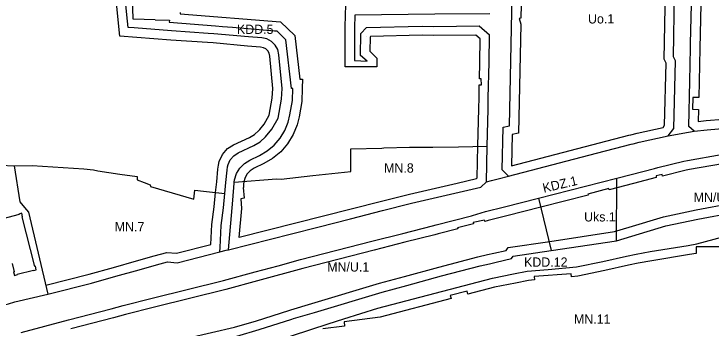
# Model space of a CAD drawing. Extents: x 7414808 to 7417449, y 5544732 to 5546764.
# Drawn here: x 7415519.6 to 7415895.6, y 5545891.1 to 5546060.4 of the extents above; entities that cross this region are included whole.
import ezdxf

# ---------------------------------------------------------------- set-up
doc = ezdxf.new("R2010")
doc.units = 0
for name, color, linetype in [('LIN_Linie Rozgraniczajace', 7, 'Continuous'), ('LIN_nieprzekraczale linie zabudowy', 7, 'Continuous'), ('LIN_obowiązujące linie zabudowy', 7, 'Continuous'), ('TXT_Oznaczenia Przeznaczenia', 7, 'Continuous')]:
    doc.layers.add(name, color=color, linetype=linetype)

msp = doc.modelspace()

# ---------------------------------------------------------------- linework, layer by layer
at = {"layer": 'LIN_Linie Rozgraniczajace'}
for p, q in [((7415595.79, 5546057.22), (7415583.85, 5546057.58)), ((7415774.51, 5545969.95), (7415774.77, 5545989.18))]:
    msp.add_line(p, q, dxfattribs=at)
for points in [[(7415786.28, 5545973), (7415782.94, 5545976.32), (7415783.43, 5545999.34), (7415786.84, 5546000.16), (7415788.5, 5546079.24), (7415788.63, 5546085.44), (7415785.3, 5546088.86)], [(7415872.46, 5545994.8), (7415875.55, 5545998.59), (7415876.38, 5546035.06), (7415875.3, 5546037.23), (7415875.94, 5546071.67), (7415877.25, 5546073.42), (7415877.59, 5546088.6)], [(7415583.85, 5546057.58), (7415583.43, 5546075.3), (7415573.8, 5546078.32), (7415564.97, 5546079.11), (7415559.81, 5546079.62), (7415556.94, 5546079.1), (7415546.52, 5546080.39), (7415513.83, 5546084.43), (7415510.82, 5546081.8), (7415559.62, 5546075.78), (7415564.88, 5546077.31), (7415573.69, 5546075.93), (7415579.48, 5546070.64)], [(7415886.52, 5545997.16), (7415883.58, 5545999.68), (7415884.13, 5546024.12), (7415884.54, 5546042.1), (7415884.6, 5546044.49), (7415885.08, 5546065.59), (7415885.49, 5546083.7)], [(7415581.19, 5546053.19), (7415580.8, 5546056.61), (7415579.98, 5546065.34)], [(7415776.33, 5546060.55), (7415746.7, 5546060.31), (7415703.42, 5546059.82), (7415703.26, 5546052.85)], [(7415595.79, 5546057.22), (7415603.45, 5546057.06), (7415603.37, 5546056.07), (7415628.32, 5546054.09), (7415632.14, 5546053.73), (7415637.4, 5546053.25)], [(7415709.7, 5546053.2), (7415739.75, 5546053.91), (7415746.1, 5546053.72), (7415770.52, 5546053.93), (7415776.17, 5546049.22)], [(7415633.35, 5545963.71), (7415633.92, 5545969.5), (7415634.52, 5545976.22), (7415634.79, 5545977.98), (7415635.09, 5545979.29), (7415636.26, 5545981.86), (7415638.11, 5545983.99), (7415640.48, 5545985.52), (7415648.92, 5545989.43), (7415652.36, 5545991.46), (7415655.35, 5545994.12), (7415658.73, 5545998.23), (7415662.07, 5546004.15), (7415663.88, 5546014.5), (7415664.25, 5546020.31), (7415662.54, 5546038.46), (7415661.88, 5546041.21), (7415660.49, 5546043.66), (7415658.46, 5546045.62), (7415655.97, 5546046.94), (7415653.37, 5546047.5), (7415646.05, 5546048.07), (7415627.36, 5546049.75), (7415624.37, 5546049.96), (7415604.61, 5546051.36), (7415584.37, 5546052.96), (7415581.19, 5546053.19)], [(7415637.4, 5546053.25), (7415660.17, 5546051.39), (7415661.34, 5546051.29)], [(7415638.44, 5545969.7), (7415638.62, 5545971.07), (7415639.68, 5545974.36), (7415641.47, 5545977.32), (7415643.89, 5545979.79), (7415646.81, 5545981.64), (7415651.96, 5545984.12), (7415656.18, 5545986.61), (7415659.95, 5545989.74), (7415663.15, 5545993.44), (7415665.7, 5545997.61), (7415667.55, 5546002.15), (7415668.48, 5546005.98), (7415669.85, 5546013.79), (7415670.05, 5546020.27), (7415669.32, 5546020.27), (7415666.3, 5546046.51), (7415662.53, 5546050.29), (7415661.34, 5546051.29)], [(7415703.26, 5546052.85), (7415703.22, 5546035.29), (7415710.15, 5546035.03), (7415706.44, 5546037.97), (7415706.75, 5546049.91), (7415709.7, 5546053.2)], [(7415774.77, 5545989.18), (7415775.35, 5546009.15), (7415775.46, 5546015.21), (7415775.86, 5546034.18), (7415776.17, 5546049.22)], [(7415872.46, 5545994.8), (7415883.51, 5545996.64), (7415886.52, 5545997.16)], [(7415886.52, 5545997.16), (7415893.57, 5545997.99), (7415916.2, 5545999.89)], [(7415786.28, 5545973), (7415829.7, 5545984.27), (7415852.48, 5545990.18), (7415853.52, 5545990.42), (7415856.87, 5545991.21), (7415872.46, 5545994.8)], [(7415638.44, 5545969.7), (7415661.14, 5545971.45), (7415663.73, 5545971.34), (7415680.75, 5545973.37), (7415701.28, 5545975.47), (7415701.34, 5545987.72), (7415717.94, 5545988.14), (7415719.06, 5545988.16), (7415732.87, 5545988.55), (7415737.16, 5545988.56), (7415745.56, 5545988.58), (7415759.37, 5545988.87), (7415774.77, 5545989.18)], [(7415844.76, 5545971.84), (7415852.47, 5545973.82), (7415865.1, 5545977.09), (7415866.9, 5545977.56), (7415880.97, 5545980.98), (7415882.96, 5545981.47), (7415901.09, 5545984.65), (7415911.16, 5545985.54), (7415914.44, 5545985.83), (7415927.64, 5545986.05), (7415944.27, 5545986.35), (7415954.23, 5545986.43), (7415968.21, 5545986.01), (7415974.4, 5545985.57), (7415988.52, 5545984.56)], [(7415512.41, 5545978.97), (7415519.74, 5545978.47)], [(7415519.74, 5545978.47), (7415529.45, 5545978.65), (7415546.1, 5545977.59), (7415557.27, 5545976.87), (7415562.46, 5545976.39), (7415564.78, 5545975.77), (7415576.64, 5545974.08), (7415586.04, 5545972.73), (7415586.03, 5545971.04), (7415589.78, 5545969.57), (7415593.1, 5545968.28), (7415593.23, 5545967.31), (7415616.56, 5545960.53), (7415617.16, 5545965.37), (7415621.84, 5545964.84), (7415633.35, 5545963.71)], [(7415519.74, 5545978.47), (7415522.67, 5545959.21), (7415525.28, 5545956.13), (7415527.46, 5545953.55), (7415537.93, 5545909.37)], [(7415774.51, 5545969.95), (7415777.24, 5545970.65), (7415780.77, 5545971.57), (7415786.28, 5545973)], [(7415802.62, 5545961.02), (7415844.76, 5545971.84)], [(7415844.58, 5545938.19), (7415852.82, 5545940.7), (7415871.18, 5545946.15), (7415888.53, 5545949.83), (7415907.71, 5545953.42), (7415917.62, 5545955.43), (7415930.1, 5545957.84), (7415946.29, 5545960.61), (7415967.66, 5545962.35), (7415973.92, 5545962.82), (7415980.78, 5545963.53), (7415981.89, 5545963.65), (7415985.36, 5545964.57), (7415992.58, 5545970.49), (7415994.76, 5545972.26)], [(7415844.58, 5545938.19), (7415844.76, 5545971.84)], [(7415635.33, 5545933.34), (7415669.3, 5545941.96), (7415683.46, 5545945.55), (7415701.19, 5545950.05), (7415718.45, 5545954.43), (7415733.37, 5545958.27), (7415734.11, 5545958.47), (7415759.74, 5545964.4), (7415771.47, 5545967.08), (7415774.51, 5545969.95)], [(7415635.33, 5545933.34), (7415637.71, 5545959.95), (7415638.37, 5545969.19), (7415638.44, 5545969.7)], [(7415630.55, 5545932.12), (7415630.77, 5545934.53), (7415631.39, 5545946.42), (7415632.55, 5545955.96), (7415633.35, 5545963.71)], [(7415523.4, 5545888.77), (7415548.92, 5545895.57), (7415571.98, 5545901.49), (7415578.52, 5545903.17), (7415594.12, 5545907.16), (7415632.68, 5545916.73), (7415649.68, 5545921.35), (7415662.13, 5545924.72), (7415674.21, 5545927.99), (7415712.72, 5545938), (7415729.3, 5545942.15), (7415745.31, 5545946.18), (7415747.25, 5545946.68), (7415766.4, 5545951.66), (7415766.99, 5545951.81), (7415774, 5545953.91), (7415784.27, 5545956.51), (7415802.62, 5545961.02)], [(7415802.62, 5545961.02), (7415809.43, 5545932.85)], [(7415614.98, 5545867.62), (7415615.82, 5545869.06), (7415617.23, 5545869.94), (7415617.57, 5545870.05), (7415623.24, 5545871.85), (7415644.1, 5545878.69), (7415659.92, 5545883.83), (7415689.07, 5545893.3), (7415697.47, 5545896.12), (7415715.84, 5545901.77), (7415777.73, 5545917.93), (7415789.12, 5545920.23), (7415796.38, 5545921.71), (7415807.79, 5545922.67), (7415823.09, 5545924.04), (7415837.24, 5545927.04), (7415849.99, 5545929.82), (7415855.28, 5545930.97), (7415862.77, 5545932.27), (7415883.2, 5545935.59), (7415887.87, 5545936.49), (7415911.39, 5545942.72)], [(7415809.43, 5545932.85), (7415844.58, 5545938.19)], [(7415630.55, 5545932.12), (7415634.02, 5545933), (7415635.33, 5545933.34)], [(7415537.93, 5545909.37), (7415561.48, 5545915.35), (7415574.55, 5545919.01), (7415587.09, 5545922.52), (7415596.54, 5545925.17), (7415602.42, 5545926.8), (7415607.64, 5545926.31), (7415630.55, 5545932.12)], [(7415596.59, 5545878.03), (7415614.73, 5545880.93), (7415639.79, 5545886.66), (7415651.81, 5545890.22), (7415669.44, 5545895.85), (7415670.41, 5545896.15), (7415681.78, 5545899.54), (7415718.18, 5545910.49), (7415731.5, 5545914.06), (7415750.14, 5545919.17), (7415770.99, 5545924.57), (7415776.17, 5545925.79), (7415779.64, 5545926.58), (7415788.05, 5545928.54), (7415788.96, 5545929.82), (7415809.43, 5545932.85)], [(7415495.49, 5545898.77), (7415516.69, 5545904.1), (7415519.97, 5545905.14), (7415537.93, 5545909.37)]]:
    msp.add_lwpolyline(points, dxfattribs=at)
at = {"layer": 'LIN_nieprzekraczale linie zabudowy'}
for points in [[(7415890.76, 5546095.52), (7415890.07, 5546065.48), (7415889.54, 5546041.99)], [(7415889.54, 5546041.99), (7415889.13, 5546024), (7415888.94, 5546015.32), (7415885.81, 5546015.38), (7415885.66, 5546009.07), (7415888.79, 5546008.99), (7415888.64, 5546002.44), (7415893.07, 5546002.97), (7415911.27, 5546004.49), (7415911.91, 5546041.44), (7415913.83, 5546094.61)], [(7415793.67, 5546087.43), (7415793.06, 5546058.23), (7415792.16, 5546057.98), (7415792.99, 5546054.98), (7415791.76, 5545996.19), (7415788.34, 5545995.38), (7415787.99, 5545978.61), (7415851.29, 5545995.04), (7415852.38, 5545995.29), (7415855.74, 5545996.08), (7415869.71, 5545999.29), (7415870.59, 5546000.39), (7415871.35, 5546033.94), (7415870.28, 5546036.1), (7415870.97, 5546073.38)], [(7415576.63, 5546048.51), (7415574.66, 5546068.27)], [(7415609.26, 5546061.21), (7415609.25, 5546060.41), (7415663.34, 5546056.14), (7415671.07, 5546048.81), (7415673.77, 5546025.29), (7415675.21, 5546025.3), (7415675.05, 5546020.34), (7415674.83, 5546013.28), (7415673.38, 5546004.96), (7415672.32, 5546000.61), (7415670.18, 5545995.35), (7415667.2, 5545990.48), (7415663.46, 5545986.16), (7415659.07, 5545982.5), (7415654.32, 5545979.71), (7415649.24, 5545977.26), (7415647.06, 5545975.88), (7415645.45, 5545974.24), (7415644.26, 5545972.27), (7415643.51, 5545969.96), (7415643.34, 5545968.68), (7415643.46, 5545966.92), (7415643.31, 5545966.91), (7415643.84, 5545961.02), (7415641.88, 5545960.81), (7415642.34, 5545955.61), (7415640.94, 5545939.92)], [(7415641.13, 5545940), (7415717.21, 5545959.28), (7415732.92, 5545963.33), (7415758.62, 5545969.27), (7415769.03, 5545971.65), (7415769.54, 5545972.13), (7415769.77, 5545989.25), (7415769.77, 5545989.33), (7415770.35, 5546009.27), (7415770.46, 5546015.3), (7415770.6, 5546022.25), (7415771.73, 5546022.28), (7415771.64, 5546025.41), (7415770.67, 5546025.4), (7415770.86, 5546034.29), (7415771.12, 5546046.92), (7415768.73, 5546048.91), (7415746.05, 5546048.72), (7415739.73, 5546048.91), (7415711.98, 5546048.25), (7415711.7, 5546047.94), (7415711.5, 5546040.34), (7415715.35, 5546036.64), (7415715.33, 5546031.84), (7415698.21, 5546031.88), (7415698.26, 5546052.86), (7415698.26, 5546052.96), (7415698.42, 5546060.08), (7415698.53, 5546064.76)], [(7415536.78, 5545914.24), (7415560.19, 5545920.18), (7415573.2, 5545923.82), (7415585.74, 5545927.33), (7415595.2, 5545929.99), (7415601.97, 5545931.86), (7415607.25, 5545931.37), (7415625.84, 5545936.09), (7415626.41, 5545946.85), (7415627.59, 5545956.52), (7415628.37, 5545964.2), (7415628.95, 5545969.97), (7415629.55, 5545976.83), (7415629.88, 5545978.91), (7415630.32, 5545980.9), (7415632.02, 5545984.59), (7415634.79, 5545987.8), (7415638.06, 5545989.91), (7415646.6, 5545993.86), (7415649.39, 5545995.51), (7415651.75, 5545997.64), (7415652.16, 5545998.11), (7415654.59, 5546001.07), (7415657.29, 5546005.86), (7415658.91, 5546015.09), (7415659.24, 5546020.23), (7415657.6, 5546037.64), (7415657.19, 5546039.35), (7415656.5, 5546040.56), (7415655.49, 5546041.53), (7415654.24, 5546042.19), (7415652.65, 5546042.54), (7415645.63, 5546043.09), (7415626.96, 5546044.77), (7415624.02, 5546044.97), (7415604.24, 5546046.37), (7415576.63, 5546048.51)], [(7415709.82, 5546048.2), (7415709.84, 5546048.2)], [(7415901.74, 5545979.69), (7415883.99, 5545976.57), (7415882.16, 5545976.12), (7415869.38, 5545973.02), (7415869.22, 5545973.79), (7415865.93, 5545973.09), (7415866.1, 5545972.18), (7415853.72, 5545968.98), (7415840.71, 5545965.64), (7415840.54, 5545966.3), (7415829.19, 5545963.23), (7415829.34, 5545962.72), (7415803.84, 5545956.17), (7415785.48, 5545951.66), (7415775.32, 5545949.09), (7415773.53, 5545948.56), (7415773.48, 5545949.16), (7415767.34, 5545947.96), (7415767.49, 5545947.27), (7415758.83, 5545945.1), (7415758.96, 5545944.56), (7415748.5, 5545941.84), (7415746.54, 5545941.33), (7415730.52, 5545937.3), (7415713.96, 5545933.16), (7415675.49, 5545923.16), (7415650.99, 5545916.52), (7415633.94, 5545911.89), (7415595.34, 5545902.31), (7415579.76, 5545898.33), (7415573.22, 5545896.65), (7415550.19, 5545890.73)], [(7415613.78, 5545885.84), (7415638.52, 5545891.5), (7415650.34, 5545895), (7415667.94, 5545900.62), (7415668.96, 5545900.93), (7415680.35, 5545904.33), (7415716.81, 5545915.3), (7415730.19, 5545918.89), (7415748.85, 5545924), (7415769.79, 5545929.42), (7415775.04, 5545930.66), (7415778.52, 5545931.45), (7415785.07, 5545932.98), (7415786.12, 5545934.45), (7415808.69, 5545937.79), (7415843.47, 5545943.08), (7415851.38, 5545945.49), (7415869.95, 5545951), (7415887.55, 5545954.73), (7415906.75, 5545958.33)], [(7415901.54, 5545934.94), (7415887.66, 5545934.96), (7415887.58, 5545931.34), (7415884.07, 5545930.67), (7415863.6, 5545927.34), (7415856.24, 5545926.06), (7415851.05, 5545924.93), (7415838.29, 5545922.15), (7415823.83, 5545919.09), (7415820.36, 5545918.78), (7415820.18, 5545920.39), (7415800.27, 5545918.88), (7415800.41, 5545917.03), (7415797.09, 5545916.75), (7415790.11, 5545915.33), (7415778.86, 5545913.06), (7415764.49, 5545909.31), (7415764.02, 5545911.04), (7415754.93, 5545908.63), (7415755.41, 5545906.94), (7415717.21, 5545896.96), (7415697.66, 5545894.41), (7415697.96, 5545892.11), (7415686.2, 5545890.6)]]:
    msp.add_lwpolyline(points, dxfattribs=at)
at = {"layer": 'LIN_obowiązujące linie zabudowy'}
msp.add_lwpolyline([(7415518.57, 5545925.89), (7415519.68, 5545921.45), (7415519.39, 5545921.38), (7415519.87, 5545919.48), (7415521.41, 5545919.87), (7415521.34, 5545920.16), (7415530.05, 5545922.35), (7415530.11, 5545922.08), (7415531.63, 5545922.45), (7415531.16, 5545924.37), (7415530.87, 5545924.3), (7415530.87, 5545924.3), (7415523.94, 5545951.01), (7415524.25, 5545951.09), (7415523.75, 5545952.96), (7415522.28, 5545952.57), (7415522.34, 5545952.33), (7415513.63, 5545950.03)], dxfattribs=at)

# ---------------------------------------------------------------- texts
at = {"layer": 'TXT_Oznaczenia Przeznaczenia'}
for s, p in [('Uo.1', (7415829.25, 5546055.28)), ('KDD.5', (7415639.88, 5546049.65)), ('MN.8', (7415719.26, 5545974.88)), ('MN/U.2', (7415886.25, 5545959.07)), ('Uks.1', (7415827.13, 5545948.55)), ('MN.7', (7415573.95, 5545943.18)), ('MN/U.1', (7415688.56, 5545921.56)), ('KDD.12', (7415794.76, 5545924.15)), ('MN.11', (7415821.66, 5545893.41))]:
    msp.add_text(s, height=5, dxfattribs=at).set_placement(p)
msp.add_text('KDZ.1', height=5, rotation=13.2497, dxfattribs=at).set_placement((7415805.44, 5545963.99))

doc.saveas('drawing.dxf')
